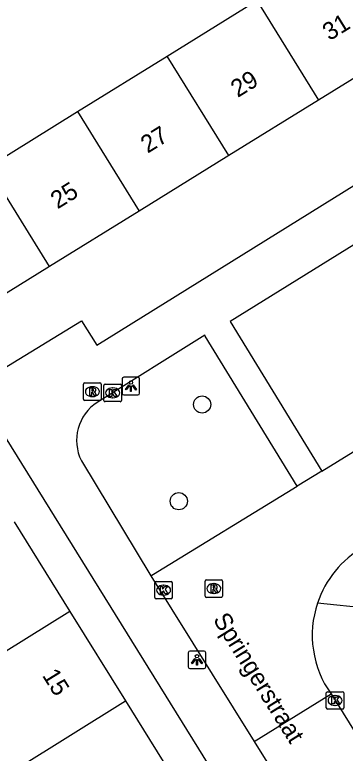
# Model space of a CAD drawing. Extents: x 160037 to 160839, y 385326 to 386441.
# Drawn here: x 160308.71 to 160327.51, y 386076.5 to 386118.52 of the extents above; entities that cross this region are included whole.
import ezdxf

# ---------------------------------------------------------------- set-up
doc = ezdxf.new("R2010")
doc.units = 0
for name, color, linetype in [('IMGEO_Boom', 7, 'Continuous'), ('IMGEO_Kolk', 7, 'Continuous'), ('IMGEO_Lichtpunt', 7, 'Continuous'), ('IMGEO_Openbare_ruimte_label', 7, 'Continuous'), ('IMGEO_Pand', 7, 'Continuous'), ('IMGEO_Pand_nummerreeks', 7, 'Continuous'), ('IMGEO_Rijbaan_lokaal_open', 7, 'Continuous'), ('IMGEO_Rioolput', 7, 'Continuous'), ('IMGEO_Voetpad_open', 7, 'Continuous')]:
    doc.layers.add(name, color=color, linetype=linetype)

msp = doc.modelspace()

# ---------------------------------------------------------------- linework, layer by layer
at = {"layer": 'IMGEO_Boom'}
for centre in [(160319.37, 386096.345), (160318.042, 386090.841)]:
    msp.add_circle(centre, 0.489, dxfattribs=at)
at = {"layer": 'IMGEO_Kolk'}
for p, q in [((160313.783, 386096.581), (160313.783, 386097.433)), ((160313.858, 386097.507), (160314.71, 386097.507)), ((160314.271, 386097.287), (160314.296, 386097.287)), ((160314.784, 386097.433), (160314.784, 386096.581)), ((160314.294, 386096.727), (160314.269, 386096.727)), ((160314.71, 386096.507), (160313.858, 386096.507)), ((160316.674, 386085.354), (160316.674, 386086.206)), ((160316.749, 386086.28), (160317.601, 386086.28)), ((160317.675, 386086.206), (160317.675, 386085.354)), ((160317.162, 386086.06), (160317.187, 386086.06)), ((160317.185, 386085.5), (160317.16, 386085.5)), ((160317.601, 386085.28), (160316.749, 386085.28)), ((160326.433, 386079.078), (160326.433, 386079.93)), ((160326.508, 386080.004), (160327.36, 386080.004)), ((160327.434, 386079.93), (160327.434, 386079.078)), ((160326.921, 386079.784), (160326.946, 386079.784)), ((160326.944, 386079.224), (160326.919, 386079.224)), ((160327.36, 386079.004), (160326.508, 386079.004))]:
    msp.add_line(p, q, dxfattribs=at)
for points in [[(160313.783, 386096.581), (160313.783, 386097.433)], [(160313.858, 386097.507), (160314.71, 386097.507)], [(160314.104, 386097.207), (160314.227, 386097.207), (160314.227, 386097.056), (160314.357, 386097.207), (160314.521, 386097.207), (160314.375, 386097.056), (160314.528, 386096.807), (160314.376, 386096.807), (160314.291, 386096.971), (160314.227, 386096.904), (160314.227, 386096.807), (160314.104, 386096.807), (160314.104, 386097.207)], [(160314.784, 386097.433), (160314.784, 386096.581)], [(160314.71, 386096.507), (160313.858, 386096.507)], [(160316.674, 386085.354), (160316.674, 386086.206)], [(160316.749, 386086.28), (160317.601, 386086.28)], [(160317.675, 386086.206), (160317.675, 386085.354)], [(160316.995, 386085.98), (160317.118, 386085.98), (160317.118, 386085.829), (160317.248, 386085.98), (160317.412, 386085.98), (160317.266, 386085.829), (160317.419, 386085.58), (160317.267, 386085.58), (160317.182, 386085.744), (160317.118, 386085.677), (160317.118, 386085.58), (160316.995, 386085.58), (160316.995, 386085.98)], [(160317.601, 386085.28), (160316.749, 386085.28)], [(160326.433, 386079.078), (160326.433, 386079.93)], [(160326.508, 386080.004), (160327.36, 386080.004)], [(160327.434, 386079.93), (160327.434, 386079.078)], [(160326.754, 386079.704), (160326.877, 386079.704), (160326.877, 386079.553), (160327.007, 386079.704), (160327.171, 386079.704), (160327.025, 386079.553), (160327.178, 386079.304), (160327.026, 386079.304), (160326.941, 386079.468), (160326.877, 386079.401), (160326.877, 386079.304), (160326.754, 386079.304), (160326.754, 386079.704)], [(160327.36, 386079.004), (160326.508, 386079.004)]]:
    msp.add_lwpolyline(points, dxfattribs=at)
for centre, start, end in [((160313.86, 386097.431), 91.552, 178.448), ((160313.86, 386097.431), 91.552, 178.448), ((160314.708, 386097.431), 1.552, 88.448), ((160314.708, 386097.431), 1.552, 88.448), ((160313.86, 386096.583), 181.552, 268.448), ((160313.86, 386096.583), 181.552, 268.448), ((160314.708, 386096.583), 271.552, 358.448), ((160314.708, 386096.583), 271.552, 358.448), ((160316.751, 386086.204), 91.552, 178.448), ((160316.751, 386086.204), 91.552, 178.448), ((160317.599, 386086.204), 1.552, 88.448), ((160317.599, 386086.204), 1.552, 88.448), ((160316.751, 386085.356), 181.552, 268.448), ((160316.751, 386085.356), 181.552, 268.448), ((160317.599, 386085.356), 271.552, 358.448), ((160317.599, 386085.356), 271.552, 358.448), ((160326.51, 386079.928), 91.552, 178.448), ((160326.51, 386079.928), 91.552, 178.448), ((160327.358, 386079.928), 1.552, 88.448), ((160327.358, 386079.928), 1.552, 88.448), ((160326.51, 386079.08), 181.552, 268.448), ((160326.51, 386079.08), 181.552, 268.448), ((160327.358, 386079.08), 271.552, 358.448), ((160327.358, 386079.08), 271.552, 358.448)]:
    msp.add_arc(centre, 0.0765, start, end, dxfattribs=at)
for centre, major_axis, ratio, start_param, end_param in [((160314.27, 386097.007), (-0.387, 0.002), 0.722429, 4.712389, 7.853982), ((160314.295, 386097.007), (-0.39, 0.002), 0.717154, 1.570796, 4.712389), ((160317.161, 386085.78), (-0.387, 0.002), 0.722429, 4.712389, 7.853982), ((160317.186, 386085.78), (-0.39, 0.002), 0.717154, 1.570796, 4.712389), ((160326.92, 386079.504), (-0.387, 0.002), 0.722429, 4.712389, 7.853982), ((160326.945, 386079.504), (-0.39, 0.002), 0.717154, 1.570796, 4.712389)]:
    msp.add_ellipse(centre, major_axis=major_axis, ratio=ratio, start_param=start_param, end_param=end_param, dxfattribs=at)
at = {"layer": 'IMGEO_Lichtpunt'}
for p, q in [((160314.82, 386097.797), (160314.82, 386096.99)), ((160314.82, 386097.797), (160314.82, 386096.99)), ((160315.722, 386097.892), (160314.914, 386097.892)), ((160315.722, 386097.892), (160314.914, 386097.892)), ((160315.816, 386096.99), (160315.816, 386097.797)), ((160315.816, 386096.99), (160315.816, 386097.797)), ((160314.914, 386096.896), (160315.722, 386096.896)), ((160314.914, 386096.896), (160315.722, 386096.896)), ((160318.578, 386082.223), (160318.578, 386081.416)), ((160318.578, 386082.223), (160318.578, 386081.416)), ((160319.48, 386082.318), (160318.672, 386082.318)), ((160319.48, 386082.318), (160318.672, 386082.318)), ((160319.574, 386081.416), (160319.574, 386082.223)), ((160319.574, 386081.416), (160319.574, 386082.223)), ((160318.672, 386081.322), (160319.48, 386081.322)), ((160318.672, 386081.322), (160319.48, 386081.322))]:
    msp.add_line(p, q, dxfattribs=at)
for points in [[(160315.194, 386097.461), (160315.233, 386097.433), (160315.045, 386097.171), (160315.007, 386097.198), (160315.194, 386097.461)], [(160315.296, 386097.413), (160315.343, 386097.413), (160315.343, 386097.091), (160315.296, 386097.091), (160315.296, 386097.413)], [(160315.406, 386097.433), (160315.444, 386097.46), (160315.631, 386097.198), (160315.592, 386097.17), (160315.406, 386097.433)], [(160318.952, 386081.887), (160318.991, 386081.859), (160318.803, 386081.597), (160318.765, 386081.624), (160318.952, 386081.887)], [(160319.054, 386081.839), (160319.101, 386081.839), (160319.101, 386081.517), (160319.054, 386081.517), (160319.054, 386081.839)], [(160319.164, 386081.859), (160319.202, 386081.886), (160319.389, 386081.624), (160319.35, 386081.596), (160319.164, 386081.859)]]:
    msp.add_lwpolyline(points, dxfattribs=at)
for centre in [(160315.319, 386097.595), (160319.077, 386082.021)]:
    msp.add_circle(centre, 0.0994, dxfattribs=at)
for centre, start, end in [((160314.914, 386097.797), 90, 180), ((160314.914, 386097.797), 90, 180), ((160315.722, 386097.797), 0, 90), ((160315.722, 386097.797), 0, 90), ((160314.914, 386096.99), 180, 270), ((160314.914, 386096.99), 180, 270), ((160315.722, 386096.99), 270, 0), ((160315.722, 386096.99), 270, 360), ((160318.672, 386082.223), 90, 180), ((160318.672, 386082.223), 90, 180), ((160319.48, 386082.223), 0, 90), ((160319.48, 386082.223), 0, 90), ((160318.672, 386081.416), 180, 270), ((160318.672, 386081.416), 180, 270), ((160319.48, 386081.416), 270, 0), ((160319.48, 386081.416), 270, 360)]:
    msp.add_arc(centre, 0.0946, start, end, dxfattribs=at)
at = {"layer": 'IMGEO_Pand'}
for points in [[(160317.38, 386116.171), (160322.483, 386119.328)], [(160322.483, 386119.328), (160325.988, 386113.663)], [(160331.09, 386116.819), (160325.988, 386113.663)], [(160312.278, 386113.014), (160317.38, 386116.171)], [(160320.885, 386110.506), (160317.38, 386116.171)], [(160325.988, 386113.663), (160320.885, 386110.506)], [(160307.175, 386109.857), (160312.278, 386113.014)], [(160312.278, 386113.014), (160315.783, 386107.349)], [(160320.885, 386110.506), (160315.783, 386107.349)], [(160310.68, 386104.192), (160307.175, 386109.857)], [(160315.783, 386107.349), (160310.68, 386104.192)], [(160310.68, 386104.192), (160305.578, 386101.035)], [(160308.677, 386089.663), (160311.847, 386084.569)], [(160311.847, 386084.569), (160305.592, 386080.676)], [(160311.847, 386084.569), (160315.017, 386079.474)], [(160308.749, 386075.574), (160315.017, 386079.474)], [(160315.017, 386079.474), (160318.187, 386074.379)]]:
    msp.add_lwpolyline(points, dxfattribs=at)
at = {"layer": 'IMGEO_Rijbaan_lokaal_open'}
for points in [[(160326.17, 386092.56), (160327.96, 386093.66), (160328.086, 386093.742)], [(160326.17, 386092.56), (160324.78, 386091.706)], [(160316.452, 386086.59), (160316.612, 386086.688), (160324.78, 386091.706)], [(160316.452, 386086.59), (160322.334, 386077.175)], [(160322.334, 386077.175), (160326.703, 386079.873)], [(160326.703, 386079.873), (160330.953, 386073.039)], [(160322.334, 386077.175), (160326.397, 386070.67)]]:
    msp.add_lwpolyline(points, dxfattribs=at)
for centre, radius, start, end in [((160331.405, 386083.214), 5.772, 119.9097, 161.5135), ((160331.398, 386083.217), 5.764, 161.5219, 215.4605)]:
    msp.add_arc(centre, radius, start, end, dxfattribs=at)
at = {"layer": 'IMGEO_Rioolput'}
for p, q in [((160312.702, 386097.578), (160313.554, 386097.578)), ((160312.627, 386096.652), (160312.627, 386097.504)), ((160313.115, 386097.358), (160313.14, 386097.358)), ((160313.628, 386097.504), (160313.628, 386096.652)), ((160313.138, 386096.798), (160313.113, 386096.798)), ((160313.554, 386096.578), (160312.702, 386096.578)), ((160319.536, 386085.445), (160319.536, 386086.297)), ((160319.611, 386086.371), (160320.463, 386086.371)), ((160320.537, 386086.297), (160320.537, 386085.445)), ((160320.024, 386086.151), (160320.049, 386086.151)), ((160320.463, 386085.371), (160319.611, 386085.371)), ((160320.047, 386085.591), (160320.022, 386085.591))]:
    msp.add_line(p, q, dxfattribs=at)
for points in [[(160312.702, 386097.578), (160313.554, 386097.578)], [(160312.627, 386096.652), (160312.627, 386097.504)], [(160313.216, 386097.276), (160312.964, 386097.278), (160312.964, 386096.878)], [(160313.142, 386097.197), (160313.088, 386097.197), (160313.088, 386097.116)], [(160313.088, 386097.116), (160313.14, 386097.116)], [(160313.628, 386097.504), (160313.628, 386096.652)], [(160312.964, 386096.878), (160313.088, 386096.878), (160313.088, 386097.04), (160313.099, 386097.04)], [(160313.146, 386097.011), (160313.217, 386096.878), (160313.357, 386096.878), (160313.292, 386097.004)], [(160313.554, 386096.578), (160312.702, 386096.578)], [(160319.536, 386085.445), (160319.536, 386086.297)], [(160319.611, 386086.371), (160320.463, 386086.371)], [(160320.537, 386086.297), (160320.537, 386085.445)], [(160320.125, 386086.069), (160319.873, 386086.071), (160319.873, 386085.671)], [(160319.873, 386085.671), (160319.997, 386085.671), (160319.997, 386085.833), (160320.008, 386085.833)], [(160320.051, 386085.99), (160319.997, 386085.99), (160319.997, 386085.909)], [(160319.997, 386085.909), (160320.049, 386085.909)], [(160320.055, 386085.804), (160320.126, 386085.671), (160320.266, 386085.671), (160320.201, 386085.797)], [(160320.463, 386085.371), (160319.611, 386085.371)]]:
    msp.add_lwpolyline(points, dxfattribs=at)
for centre, radius, start, end in [((160312.704, 386097.502), 0.0765, 91.552, 178.448), ((160312.704, 386097.502), 0.0765, 91.552, 178.448), ((160313.552, 386097.502), 0.0765, 1.552, 88.448), ((160313.552, 386097.502), 0.0765, 1.552, 88.448), ((160313.124, 386097.305), 0.19, 274.7715, 282.9687), ((160313.148, 386097.101), 0.0964, 77.0061, 93.1865), ((160313.162, 386097.158), 0.0378, 276.6634, 79.6772), ((160313.215, 386097.166), 0.109, 350.3612, 89.416), ((160313.213, 386097.166), 0.112, 277.5842, 350.9817), ((160313.098, 386096.987), 0.0533, 26.0293, 88.6989), ((160313.197, 386096.951), 0.108, 29.5134, 73.7905), ((160312.704, 386096.654), 0.0765, 181.552, 268.448), ((160312.704, 386096.654), 0.0765, 181.552, 268.448), ((160313.552, 386096.654), 0.0765, 271.552, 358.448), ((160313.552, 386096.654), 0.0765, 271.552, 358.448), ((160319.613, 386086.295), 0.0765, 91.552, 178.448), ((160319.613, 386086.295), 0.0765, 91.552, 178.448), ((160320.461, 386086.295), 0.0765, 1.552, 88.448), ((160320.461, 386086.295), 0.0765, 1.552, 88.448), ((160320.007, 386085.78), 0.0533, 26.0293, 88.6989), ((160320.033, 386086.098), 0.19, 274.7715, 282.9687), ((160320.057, 386085.894), 0.0964, 77.0061, 93.1865), ((160320.071, 386085.951), 0.0378, 276.6634, 79.6772), ((160320.124, 386085.959), 0.109, 350.3612, 89.416), ((160320.122, 386085.959), 0.112, 277.5842, 350.9817), ((160320.106, 386085.744), 0.108, 29.5134, 73.7905), ((160319.613, 386085.447), 0.0765, 181.552, 268.448), ((160319.613, 386085.447), 0.0765, 181.552, 268.448), ((160320.461, 386085.447), 0.0765, 271.552, 358.448), ((160320.461, 386085.447), 0.0765, 271.552, 358.448)]:
    msp.add_arc(centre, radius, start, end, dxfattribs=at)
for centre, major_axis, ratio, start_param, end_param in [((160313.114, 386097.078), (-0.387, 0.002), 0.722429, 4.712389, 7.853982), ((160313.139, 386097.078), (-0.39, 0.002), 0.717154, 1.570796, 4.712389), ((160320.023, 386085.871), (-0.387, 0.002), 0.722429, 4.712389, 7.853982), ((160320.048, 386085.871), (-0.39, 0.002), 0.717154, 1.570796, 4.712389)]:
    msp.add_ellipse(centre, major_axis=major_axis, ratio=ratio, start_param=start_param, end_param=end_param, dxfattribs=at)
at = {"layer": 'IMGEO_Voetpad_open'}
for points in [[(160306.39, 386097.366), (160312.51, 386101.101), (160313.388, 386099.731), (160355.583, 386125.97), (160356.119, 386126.467)], [(160341.88, 386104.496), (160337.622, 386111.408), (160320.972, 386101.06), (160326.17, 386092.56)], [(160324.78, 386091.706), (160319.552, 386100.231), (160319.518, 386100.287), (160313.409, 386096.468)], [(160324.593, 386064.084), (160326.368, 386065.167), (160307.246, 386095.986)], [(160312.501, 386093.146), (160316.452, 386086.59)], [(160328.868, 386084.732), (160325.931, 386085.044)]]:
    msp.add_lwpolyline(points, dxfattribs=at)
msp.add_arc((160314.817, 386094.298), 2.587, 122.9847, 206.4409, dxfattribs=at)

# ---------------------------------------------------------------- texts
at = {"layer": 'IMGEO_Openbare_ruimte_label'}
msp.add_text('Springerstraat', height=1, rotation=301.8778, dxfattribs=at).set_placement((160319.959, 386084.109))
at = {"layer": 'IMGEO_Pand_nummerreeks'}
for s, rotation, p in [('31', 31.746, (160326.615, 386117.014)), ('29', 31.746, (160321.395, 386113.784)), ('27', 31.746, (160316.27, 386110.614)), ('25', 31.746, (160311.146, 386107.443)), ('15', 301.8906, (160310.246, 386080.93))]:
    msp.add_text(s, height=1, rotation=rotation, dxfattribs=at).set_placement(p)

doc.saveas('drawing.dxf')
